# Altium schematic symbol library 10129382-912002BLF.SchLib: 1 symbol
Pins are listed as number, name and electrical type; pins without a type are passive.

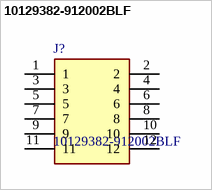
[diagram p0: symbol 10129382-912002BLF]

## 10129382-912002BLF
designator J?
Connector Header Through Hole, Right Angle 12 position 0.100" (2.54mm); Manufacturer_Name: Amphenol; Geometry.Height: 5.03mm
footprint HDRRA12W67P254_2X6_1524X254X503P
pins: 1, 2, 3, 4, 5, 6, 7, 8, 9, 10, 11, 12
